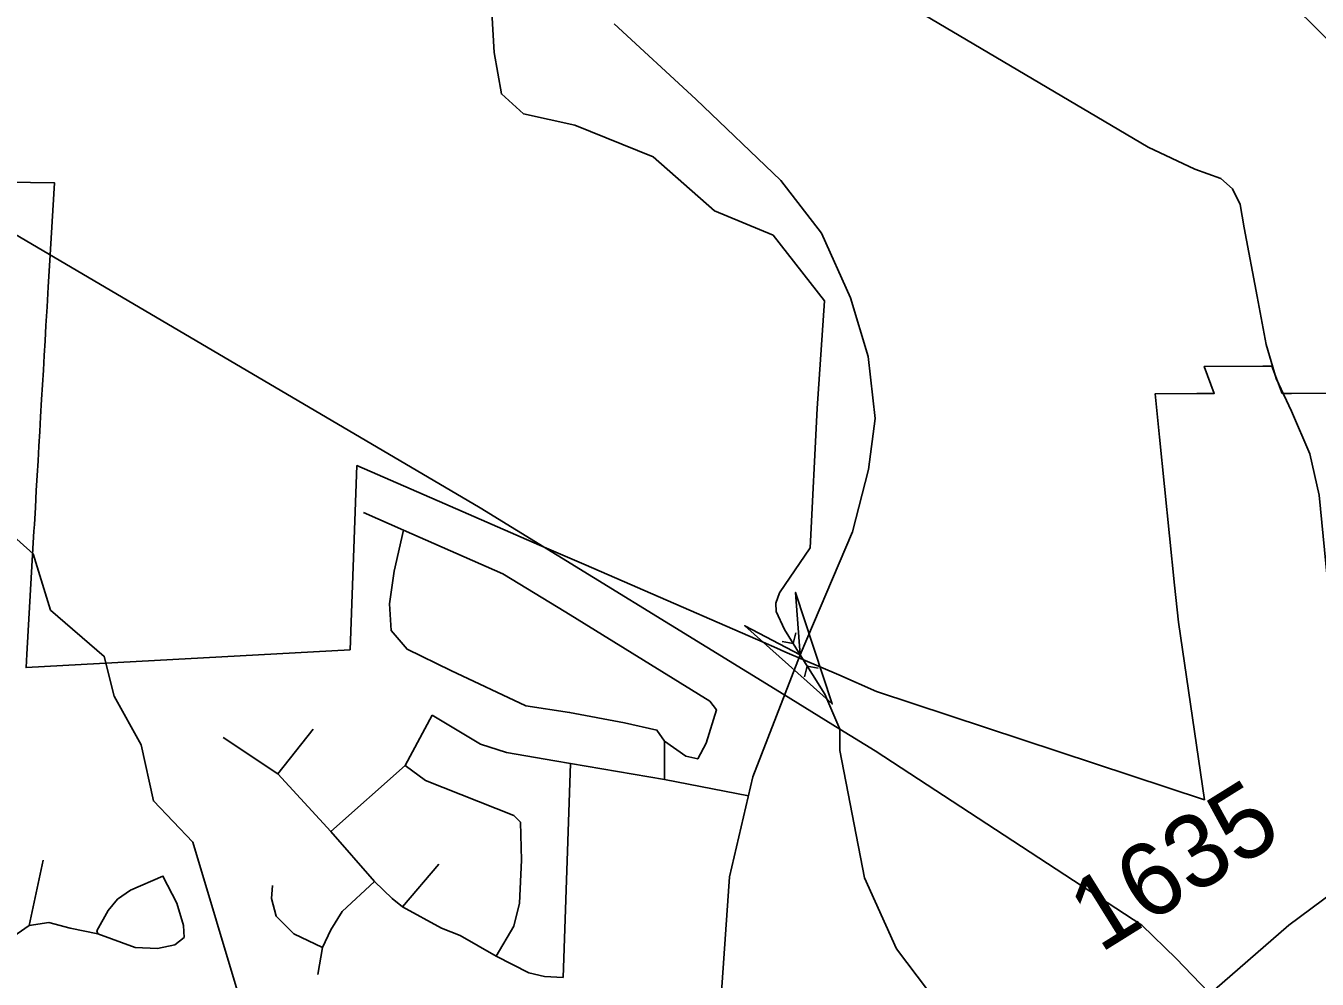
# Model space of a CAD drawing. Extents: x 2001466 to 31450019, y -30647475 to 847247.
# Drawn here: x 31427072 to 31431476, y -30631275 to -30628025 of the extents above; entities that cross this region are included whole.
import ezdxf

# ---------------------------------------------------------------- set-up
doc = ezdxf.new("R2010")
doc.units = 0
for name, color, linetype in [('Exist Hydrographic Creek Single Shore', 7, 'Continuous'), ('Exist Road Non-System Type 51', 7, 'Continuous'), ('Exist Road Secondary Structure Culvert Attributed CELL', 7, 'Continuous'), ('Exist Road Secondary Structure Culvert CELL', 7, 'Continuous'), ('Exist Road Secondary Type 51 Attributed', 7, 'Continuous'), ('Exist Road Secondary Type 51 Number Label', 7, 'Continuous'), ('Exist Utilities Electrical Transmission Line', 7, 'Continuous'), ('Map Preparation Boundary City Limit Buffer Line', 7, 'Continuous'), ('Prop Road Primary Interstate Projected', 7, 'Continuous')]:
    doc.layers.add(name, color=color, linetype=linetype)

msp = doc.modelspace()

# ---------------------------------------------------------------- linework, layer by layer
at = {"layer": 'Exist Hydrographic Creek Single Shore'}
for points in [[(31429848.3, -30630422.6), (31429797.3, -30630303.7), (31429713, -30630169.5), (31429659.2, -30630082.8), (31429630.9, -30630021.7), (31429629.8, -30629993.3), (31429642.2, -30629958.2), (31429747.6, -30629804.3), (31429771.6, -30629329.1), (31429795.6, -30628962.1), (31429620.5, -30628738.7), (31429420.5, -30628655.9), (31429211.6, -30628471.1), (31428944.4, -30628364), (31428769.5, -30628324.3), (31428694.5, -30628257.1), (31428669.4, -30628115.6), (31428651.6, -30627800.2)], [(31427952.6, -30632599.3), (31428052.4, -30632575), (31428127.5, -30632317.3), (31428118.5, -30632031.7), (31428034.6, -30631839.7), (31427884.5, -30631616.8), (31427641.5, -30630808), (31427507.6, -30630667.4), (31427465.6, -30630476.3), (31427373.5, -30630310.4), (31427339.5, -30630175.1), (31427156.6, -30630017.1), (31427097.5, -30629825.7), (31426997.4, -30629735), (31426722.5, -30629634.3), (31426246.5, -30629385), (31426121.5, -30629287.3)], [(31430215, -30631400.1), (31430041.4, -30631172), (31429932.6, -30630930.3), (31429848.5, -30630495.5), (31429848.3, -30630422.6)]]:
    msp.add_lwpolyline(points, dxfattribs=at)
at = {"layer": 'Exist Road Non-System Type 51'}
for points in [[(31431336, -30629227.3), (31431302.2, -30629111.4), (31431271.2, -30628947.6), (31431227, -30628713.1), (31431213.7, -30628633.4), (31431187.2, -30628580.3), (31431147.4, -30628544.9), (31431058.9, -30628513.9), (31430899.7, -30628438.7), (31430010.8, -30627912), (31429904.7, -30627907.6)], [(31431689.2, -30630861.5), (31431624.8, -30630731), (31431576.5, -30630542.6), (31431542.7, -30630285.7), (31431515.4, -30629950.8), (31431483.2, -30629624.7), (31431451, -30629484.5), (31431389.1, -30629338.4), (31431336, -30629227.3)], [(31428359.9, -30629744.8), (31428223.7, -30629684.6)], [(31428359.9, -30629744.8), (31428328.2, -30629884.3), (31428312.4, -30629995.2), (31428318.7, -30630087.1), (31428372.6, -30630150.5), (31428521.5, -30630223.4), (31428778, -30630343.9), (31428926.9, -30630366.1), (31429113.8, -30630400.9), (31429224.7, -30630426.3), (31429250, -30630464.3), (31429250, -30630594.3)], [(31429250, -30630464.3), (31429322.9, -30630515.1), (31429364, -30630524.6), (31429392.6, -30630470.7), (31429427.4, -30630356.6), (31429405.2, -30630328), (31428914.2, -30630023.7), (31428698.9, -30629893.8), (31428359.9, -30629744.8)], [(31428458.1, -30630375.6), (31428366.3, -30630546.8)], [(31428458.1, -30630375.6), (31428622.8, -30630473.8), (31428711.5, -30630502.4), (31428876.2, -30630530.9), (31429250, -30630594.3)], [(31427932.3, -30630575.3), (31428052.7, -30630423.1)], [(31427932.3, -30630575.3), (31427745.4, -30630451.7)], [(31428366.3, -30630546.8), (31428112.9, -30630771.8)], [(31428676.7, -30631196.6), (31428736.9, -30631095.1), (31428755.9, -30631015.9), (31428762.2, -30630870.1), (31428759, -30630740.1), (31428736.9, -30630717.9), (31428435.9, -30630597.5), (31428366.3, -30630546.8)], [(31428904.7, -30631269.5), (31428929.5, -30630539.9)], [(31428112.9, -30630771.8), (31427932.3, -30630575.3)], [(31429250, -30630594.3), (31429536.9, -30630650.1)], [(31428112.9, -30630771.8), (31428261.7, -30630943)], [(31427318.1, -30631120.5), (31427223.1, -30631101.5), (31427150.2, -30631082.4), (31427083.7, -30631092), (31427131.2, -30630870.1)], [(31428356.8, -30631028.6), (31428480.3, -30630882.8)], [(31427318.1, -30631120.5), (31427444.8, -30631168), (31427520.8, -30631171.2), (31427581, -30631158.5), (31427612.7, -30631133.2), (31427609.5, -30631092), (31427587.3, -30631015.9), (31427539.8, -30630924), (31427429, -30630971.5), (31427384.6, -30631003.2), (31427352.9, -30631041.2), (31427314.9, -30631111), (31427318.1, -30631120.5)], [(31428084.3, -30631168), (31427986.1, -30631120.5), (31427926, -30631060.3), (31427910.1, -30631000), (31427913.3, -30630955.7)], [(31428261.7, -30630943), (31428150.9, -30631044.4), (31428112.9, -30631107.8), (31428084.3, -30631168)], [(31428261.7, -30630943), (31428321.9, -30631000), (31428356.8, -30631028.6)], [(31428356.8, -30631028.6), (31428489.8, -30631101.5), (31428553.1, -30631126.8), (31428676.7, -30631196.6)], [(31427083.7, -30631092), (31427001.3, -30631149), (31426887.3, -30631101.5)], [(31428084.3, -30631168), (31428068.5, -30631260)], [(31428676.7, -30631196.6), (31428787.5, -30631253.6), (31428841.4, -30631266.3), (31428904.7, -30631269.5)]]:
    msp.add_lwpolyline(points, dxfattribs=at)
at = {"layer": 'Exist Road Secondary Structure Culvert Attributed CELL'}
msp.add_lwpolyline([(31429713, -30630169.5), (31429524.4, -30630070.1), (31429822.3, -30630336.9), (31429697.7, -30629956.8), (31429713, -30630169.5)], dxfattribs=at)
at = {"layer": 'Exist Road Secondary Structure Culvert CELL'}
for p, q in [((31429651.3, -30630123.8), (31429688.7, -30630131.2)), ((31429698, -30630094.3), (31429688.7, -30630131.2)), ((31429688.7, -30630131.2), (31429737.2, -30630207.8)), ((31429727.9, -30630244.7), (31429737.2, -30630207.8)), ((31429774.6, -30630215.1), (31429737.2, -30630207.8))]:
    msp.add_line(p, q, dxfattribs=at)
at = {"layer": 'Exist Road Secondary Type 51 Attributed'}
for points in [[(31429643, -30632481.9), (31429529.6, -30632091.4), (31429455.5, -30631772.5), (31429439.5, -30631400.5), (31429471.6, -30630927.1), (31429552.1, -30630585.7), (31429713, -30630169.5), (31429891.7, -30629750.7), (31429946.4, -30629538.1), (31429968.9, -30629364.2), (31429944.8, -30629152.4), (31429885.2, -30628952.7), (31429785.4, -30628732.1), (31429647, -30628551.7), (31429357.4, -30628274.7), (31429079, -30628017.9)], [(31429643, -30632481.9), (31429748.4, -30632452.5), (31429872.3, -30632380.1), (31430014, -30632280.2), (31430150.7, -30632207.8), (31430324.5, -30632157.8), (31430462.9, -30632103.1), (31430541.8, -30632045.9), (31430648, -30631925.1), (31430781.6, -30631738.3), (31430974.7, -30631475), (31431100.2, -30631334.9), (31431380.2, -30631090.9), (31431689.2, -30630861.5)]]:
    msp.add_lwpolyline(points, dxfattribs=at)
at = {"layer": 'Exist Utilities Electrical Transmission Line'}
msp.add_line((31429657.1, -30630305.2), (31429848.3, -30630422.6), dxfattribs=at)
for points in [[(31423969, -30626935.5), (31424644.9, -30627333.4), (31425801, -30628017.1), (31427050.2, -30628744.7), (31428621.3, -30629668.8), (31429657.1, -30630305.2)], [(31429848.3, -30630422.6), (31429968.4, -30630496.4), (31430878.3, -30631091.1), (31430996, -30631205.5), (31431105.2, -30631319.7)]]:
    msp.add_lwpolyline(points, dxfattribs=at)
at = {"layer": 'Map Preparation Boundary City Limit Buffer Line'}
for points in [[(31427101.5, -30629724.9), (31427104.8, -30629667), (31427108.1, -30629609.1), (31427111.1, -30629558.1), (31427114.1, -30629508.3), (31427117, -30629458.3), (31427119.9, -30629408.4), (31427122.8, -30629358.5), (31427126.3, -30629299.1), (31427129.3, -30629248.6), (31427132.1, -30629198.8), (31427135.1, -30629148.9), (31427138, -30629098.9), (31427141.1, -30629047.1), (31427144.6, -30628983.1), (31427148.8, -30628914.3), (31427152.9, -30628843.4), (31427170.3, -30628560.6), (31427168.3, -30628560.4), (31426768.4, -30628554.1)], [(31432009.3, -30629276.5), (31431388.3, -30629278.4), (31431357.4, -30629277.9), (31431321.8, -30629185.5), (31431291.1, -30629185.5), (31431091.1, -30629186.1), (31431125.3, -30629278.1), (31431066.3, -30629278.5), (31430924, -30629279.4), (31430938.5, -30629427.3), (31430990.1, -30629932), (31431002.9, -30630058), (31431091.6, -30630663.8), (31429973.1, -30630294.1), (31429844.6, -30630238.2), (31429661.4, -30630158.9), (31429633.9, -30630147), (31429586.9, -30630126.6), (31429157.9, -30629940.1), (31428982.8, -30629864.1), (31428824.1, -30629795.1), (31428501.1, -30629654.9), (31428201.4, -30629524.5), (31428178.1, -30630152.1), (31427072.9, -30630212.9), (31427075.6, -30630167.5), (31427100.1, -30629747.5), (31427101.5, -30629724.9)]]:
    msp.add_lwpolyline(points, dxfattribs=at)
at = {"layer": 'Prop Road Primary Interstate Projected'}
msp.add_lwpolyline([(31432138.7, -30628924.1), (31432058.2, -30628798.3), (31432005.3, -30628703.9), (31431970.6, -30628645.9), (31431909.5, -30628551.5), (31431857.2, -30628473.7), (31431790.5, -30628383.7), (31431727.1, -30628307), (31431657.5, -30628223.5), (31431552.4, -30628112.2), (31431444.2, -30628004), (31431361, -30627925.7), (31430915, -30627529.7), (31430805.7, -30627429.8), (31430756.3, -30627385.8)], dxfattribs=at)

# ---------------------------------------------------------------- texts
at = {"layer": 'Exist Road Secondary Type 51 Number Label'}
msp.add_text('1635', height=250, rotation=31.918, dxfattribs=at).set_placement((31430735.5, -30631188.9))

doc.saveas('drawing.dxf')
